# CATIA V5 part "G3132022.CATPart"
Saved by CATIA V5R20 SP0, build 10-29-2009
Part number: G3132022
Revision: 5
Definition: design
Nomenclature: G3132022
Source: made
Description: NOT SPECIFIED
Bounding box of the stored display mesh (mm): x -17 to 22, y -15.5 to 15.5, z -15.5 to 15.5
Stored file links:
  C:\Users\Raffaele\Desktop\3D X SITO CF\BOLEX\24-BUSH REF 313\G3132022.CATPart
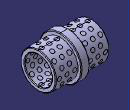
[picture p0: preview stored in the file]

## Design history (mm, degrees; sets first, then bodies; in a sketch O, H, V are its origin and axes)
Body1 "MANIFOLD_SOLID_BREP #11295" (main body)
  Solid1: solid without history
Body2 "MANIFOLD_SOLID_BREP #11438"
  Solid2: solid without history
Body3 "MANIFOLD_SOLID_BREP #11581"
  Solid3: solid without history
Body4 "MANIFOLD_SOLID_BREP #11724"
  Solid4: solid without history
Body5 "MANIFOLD_SOLID_BREP #11867"
  Solid5: solid without history
Body6 "MANIFOLD_SOLID_BREP #12012"
  Solid6: solid without history
Body7 "MANIFOLD_SOLID_BREP #12157"
  Solid7: solid without history
Body8 "MANIFOLD_SOLID_BREP #12302"
  Solid8: solid without history
Body9 "MANIFOLD_SOLID_BREP #12447"
  Solid9: solid without history
Body10 "MANIFOLD_SOLID_BREP #12592"
  Solid10: solid without history
Body11 "MANIFOLD_SOLID_BREP #12737"
  Solid11: solid without history
Body12 "MANIFOLD_SOLID_BREP #12882"
  Solid12: solid without history
Body13 "MANIFOLD_SOLID_BREP #13027"
  Solid13: solid without history
Body14 "MANIFOLD_SOLID_BREP #13172"
  Solid14: solid without history
Body15 "MANIFOLD_SOLID_BREP #13317"
  Solid15: solid without history
Body16 "MANIFOLD_SOLID_BREP #13462"
  Solid16: solid without history
Body17 "MANIFOLD_SOLID_BREP #13607"
  Solid17: solid without history
Body18 "MANIFOLD_SOLID_BREP #13752"
  Solid18: solid without history
Body19 "MANIFOLD_SOLID_BREP #13897"
  Solid19: solid without history
Body20 "MANIFOLD_SOLID_BREP #14042"
  Solid20: solid without history
Body21 "MANIFOLD_SOLID_BREP #14187"
  Solid21: solid without history
Body22 "MANIFOLD_SOLID_BREP #14334"
  Solid22: solid without history
Body23 "MANIFOLD_SOLID_BREP #14479"
  Solid23: solid without history
Body24 "MANIFOLD_SOLID_BREP #14624"
  Solid24: solid without history
Body25 "MANIFOLD_SOLID_BREP #14771"
  Solid25: solid without history
Body26 "MANIFOLD_SOLID_BREP #14916"
  Solid26: solid without history
Body27 "MANIFOLD_SOLID_BREP #15061"
  Solid27: solid without history
Body28 "MANIFOLD_SOLID_BREP #15206"
  Solid28: solid without history
Body29 "MANIFOLD_SOLID_BREP #15351"
  Solid29: solid without history
Body30 "MANIFOLD_SOLID_BREP #15496"
  Solid30: solid without history
Body31 "MANIFOLD_SOLID_BREP #15641"
  Solid31: solid without history
Body32 "MANIFOLD_SOLID_BREP #15784"
  Solid32: solid without history
Body33 "MANIFOLD_SOLID_BREP #15927"
  Solid33: solid without history
Body34 "MANIFOLD_SOLID_BREP #16072"
  Solid34: solid without history
Body35 "MANIFOLD_SOLID_BREP #16217"
  Solid35: solid without history
Body36 "MANIFOLD_SOLID_BREP #16362"
  Solid36: solid without history
Body37 "MANIFOLD_SOLID_BREP #16507"
  Solid37: solid without history
Body38 "MANIFOLD_SOLID_BREP #16654"
  Solid38: solid without history
Body39 "MANIFOLD_SOLID_BREP #16799"
  Solid39: solid without history
Body40 "MANIFOLD_SOLID_BREP #16944"
  Solid40: solid without history
Body41 "MANIFOLD_SOLID_BREP #17091"
  Solid41: solid without history
Body42 "MANIFOLD_SOLID_BREP #17236"
  Solid42: solid without history
Body43 "MANIFOLD_SOLID_BREP #17381"
  Solid43: solid without history
Body44 "MANIFOLD_SOLID_BREP #17526"
  Solid44: solid without history
Body45 "MANIFOLD_SOLID_BREP #17671"
  Solid45: solid without history
Body46 "MANIFOLD_SOLID_BREP #17816"
  Solid46: solid without history
Body47 "MANIFOLD_SOLID_BREP #17961"
  Solid47: solid without history
Body48 "MANIFOLD_SOLID_BREP #18106"
  Solid48: solid without history
Body49 "MANIFOLD_SOLID_BREP #18251"
  Solid49: solid without history
Body50 "MANIFOLD_SOLID_BREP #18396"
  Solid50: solid without history
Body51 "MANIFOLD_SOLID_BREP #18541"
  Solid51: solid without history
Body52 "MANIFOLD_SOLID_BREP #18686"
  Solid52: solid without history
Body53 "MANIFOLD_SOLID_BREP #18831"
  Solid53: solid without history
Body54 "MANIFOLD_SOLID_BREP #18976"
  Solid54: solid without history
Body55 "MANIFOLD_SOLID_BREP #19121"
  Solid55: solid without history
Body56 "MANIFOLD_SOLID_BREP #19266"
  Solid56: solid without history
Body57 "MANIFOLD_SOLID_BREP #19411"
  Solid57: solid without history
Body58 "MANIFOLD_SOLID_BREP #19556"
  Solid58: solid without history
Body59 "MANIFOLD_SOLID_BREP #19701"
  Solid59: solid without history
Body60 "MANIFOLD_SOLID_BREP #19844"
  Solid60: solid without history
Body61 "MANIFOLD_SOLID_BREP #19987"
  Solid61: solid without history
Body62 "MANIFOLD_SOLID_BREP #20130"
  Solid62: solid without history
Body63 "MANIFOLD_SOLID_BREP #20273"
  Solid63: solid without history
Body64 "MANIFOLD_SOLID_BREP #20416"
  Solid64: solid without history
Body65 "MANIFOLD_SOLID_BREP #20559"
  Solid65: solid without history
Body66 "MANIFOLD_SOLID_BREP #20704"
  Solid66: solid without history
Body67 "MANIFOLD_SOLID_BREP #20849"
  Solid67: solid without history
Body68 "MANIFOLD_SOLID_BREP #20994"
  Solid68: solid without history
Body69 "MANIFOLD_SOLID_BREP #21139"
  Solid69: solid without history
Body70 "MANIFOLD_SOLID_BREP #21284"
  Solid70: solid without history
Body71 "MANIFOLD_SOLID_BREP #21429"
  Solid71: solid without history
Body72 "MANIFOLD_SOLID_BREP #21574"
  Solid72: solid without history
Body73 "MANIFOLD_SOLID_BREP #21719"
  Solid73: solid without history
Body74 "MANIFOLD_SOLID_BREP #21866"
  Solid74: solid without history
Body75 "MANIFOLD_SOLID_BREP #22013"
  Solid75: solid without history
Body76 "MANIFOLD_SOLID_BREP #22158"
  Solid76: solid without history
Body77 "MANIFOLD_SOLID_BREP #22303"
  Solid77: solid without history
Body78 "MANIFOLD_SOLID_BREP #22448"
  Solid78: solid without history
Body79 "MANIFOLD_SOLID_BREP #22593"
  Solid79: solid without history
Body80 "MANIFOLD_SOLID_BREP #22740"
  Solid80: solid without history
Body81 "MANIFOLD_SOLID_BREP #22887"
  Solid81: solid without history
